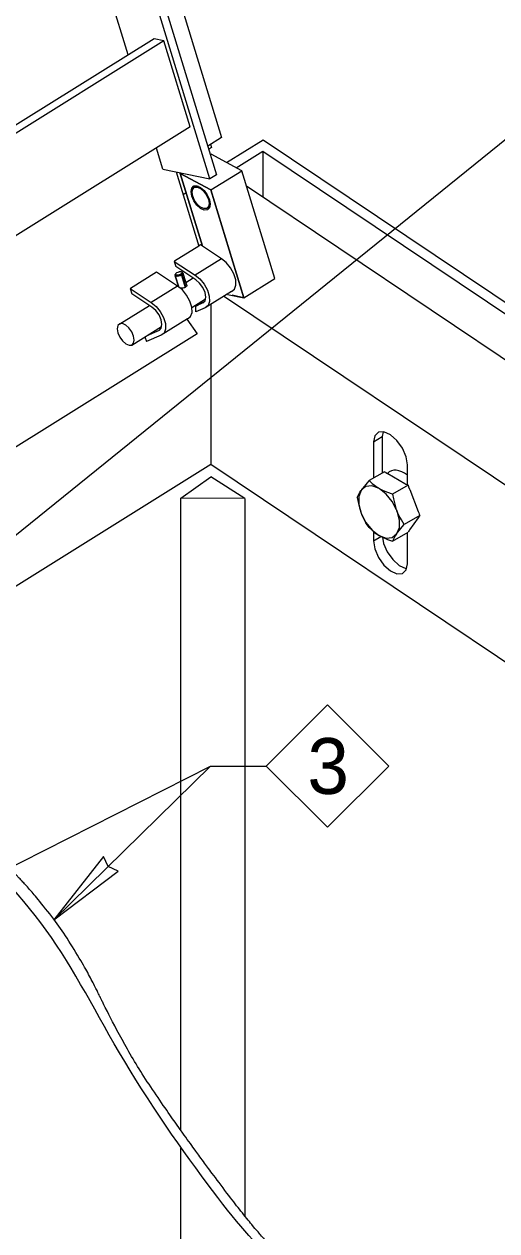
# Model space of a CAD drawing. Extents: x 99862 to 103151, y 100000 to 105076.
# Drawn here: x 100503.6 to 100639, y 100716.4 to 101062.4 of the extents above; entities that cross this region are included whole.
import ezdxf

# ---------------------------------------------------------------- set-up
doc = ezdxf.new("R2010")
doc.units = 0
for name, color, linetype in [('Level 1', 7, 'Continuous'), ('Level 11', 7, 'Continuous'), ('Level 15', 7, 'Continuous'), ('Level 20', 7, 'Continuous'), ('Level 4', 7, 'Continuous'), ('Level 6', 7, 'Continuous'), ('Level 9', 7, 'Continuous')]:
    doc.layers.add(name, color=color, linetype=linetype)

msp = doc.modelspace()

# ---------------------------------------------------------------- linework, layer by layer
at = {"layer": 'Level 1'}
for p, q in [((100533.35, 101053.56), (100518.86, 101101.05)), ((100540.84, 101058.24), (100346.19, 100936.6)), ((100543.64, 101057.65), (100346.79, 100934.64)), ((100543.34, 101020.83), (100541.5, 101026.88)), ((100571.97, 101026), (100571.97, 101012.75)), ((100556.91, 101024.96), (100557.13, 101025.1)), ((100556.91, 101024.96), (100557.13, 101025.1)), ((100556.91, 101024.96), (100557.13, 101025.1)), ((100543.34, 101020.83), (100556.78, 101018.01)), ((100547.1, 101020.04), (100553.59, 100998.77)), ((100548.32, 101019.59), (100548.55, 101019.74)), ((100548.32, 101019.59), (100548.55, 101019.74)), ((100548.32, 101019.59), (100554.67, 100998.77)), ((100557.1, 101014.86), (100565.92, 101020.37)), ((100557.1, 101014.86), (100565.92, 101020.37)), ((100553.49, 101015.87), (100552.71, 101015.82)), ((100553.06, 101016.06), (100553.08, 101016.06)), ((101027.48, 100706.93), (100567.28, 101015.9)), ((100550.03, 101013.99), (100549.12, 101013.42)), ((100555.85, 101009.55), (100556.17, 101009.75)), ((100553.59, 100998.77), (100546.64, 100994.43)), ((100546.59, 100994.39), (100552.58, 100990.43)), ((100546.97, 100990.82), (100547.06, 100990.9)), ((100549.14, 100990.92), (100549.13, 100990.93)), ((100550.17, 100987.53), (100549.14, 100990.92)), ((100546.82, 100990.5), (100546.87, 100990.63)), ((100546.88, 100990.21), (100546.83, 100990.37)), ((100546.97, 100990.82), (100546.87, 100990.63)), ((100546.88, 100990.2), (100546.88, 100990.21)), ((100546.88, 100990.2), (100546.88, 100990.21)), ((100546.88, 100990.2), (100547.91, 100987.02)), ((100547.91, 100987.02), (100546.88, 100990.2)), ((100546.96, 100990.73), (100547.16, 100990.09)), ((100547, 100990.61), (100547, 100990.6)), ((100547, 100990.6), (100547.16, 100990.09)), ((100550.17, 100987.53), (100549.66, 100989.22)), ((100549.93, 100988.32), (100552.02, 100989.62)), ((100566.53, 100983.95), (100575.35, 100989.46)), ((100533.98, 100986.56), (100540, 100982.58)), ((100562.99, 100985.78), (100555.43, 100981.06)), ((101023.58, 100673.63), (100560.7, 100984.4)), ((100530.96, 100976.46), (100539.45, 100981.77)), ((100551.61, 100981.14), (100555.54, 100983.6)), ((100554.62, 100982.54), (100553.93, 100982.59)), ((100554.8, 100982.46), (100554.81, 100982.46)), ((100557.03, 100982.02), (100557.03, 100936.2)), ((100550.42, 100977.93), (100542.86, 100973.21)), ((100550.21, 100977.8), (100553.1, 100973.63)), ((100553.1, 100973.63), (100354.56, 100849.56)), ((100542.23, 100974.6), (100542.23, 100974.6)), ((100538.2, 100972.76), (100538.62, 100971.37)), ((100381.31, 100826.39), (100557.03, 100936.2)), ((100557.03, 100936.2), (100740.05, 100813.32)), ((100548.46, 100926.44), (100557.03, 100932.64)), ((100566.76, 100926.43), (100557.03, 100932.64)), ((100566.76, 100926.43), (100548.46, 100926.44)), ((100548.46, 100745.22), (100548.46, 100926.44)), ((100548.46, 100687.98), (100548.46, 100740.07))]:
    msp.add_line(p, q, dxfattribs=at)
for points in [[(100515.46, 101160.82), (100558.67, 101019.19), (100556.78, 101018.01)], [(100519.44, 101163.3), (100560.14, 101029.92), (100556.16, 101027.43)], [(100556.78, 101018.01), (100513.57, 101159.64)], [(100551.18, 101032.93), (100543.64, 101057.65), (100540.84, 101058.24)], [(100551.18, 101032.93), (100551.18, 101032.93), (100354.33, 100909.91)], [(100561.52, 101022.73), (100572.06, 101029.21)], [(100572.09, 101029.27), (101031.93, 100720.54)], [(100556.98, 101027.95), (100557.27, 101027.02), (100556.44, 101026.5)], [(100564.32, 101021.22), (100571.97, 101026), (101030.8, 100717.96)], [(100575.35, 100989.46), (100575.35, 100989.46), (100565.92, 101020.37), (100557.13, 101025.1)], [(100561.85, 100984.93), (100566.53, 100983.95), (100575.35, 100989.46), (100565.92, 101020.37), (100557.13, 101025.1)], [(100554.67, 100998.77), (100548.32, 101019.59), (100548.55, 101019.74)], [(100554.67, 100998.77), (100548.32, 101019.59), (100557.1, 101014.86), (100566.53, 100983.95), (100563.16, 100984.66)], [(100566.53, 100983.95), (100557.1, 101014.86), (100548.32, 101019.59)], [(100556.86, 101010.77), (100556.66, 101009.75), (100556.07, 101009.17), (100555.18, 101009.11), (100554.14, 101009.58), (100553.09, 101010.5), (100552.2, 101011.74), (100551.6, 101013.11), (100551.39, 101014.4), (100551.59, 101015.42), (100552.18, 101016), (100553.06, 101016.06)], [(100555.85, 101009.55), (100555.07, 101009.5), (100554.14, 101009.91), (100553.21, 101010.73), (100552.41, 101011.84), (100551.88, 101013.05), (100551.69, 101014.2), (100551.87, 101015.1), (100552.39, 101015.62), (100552.71, 101015.82)], [(100552.39, 101015.62), (100553.18, 101015.68), (100554.11, 101015.26), (100555.04, 101014.44), (100555.83, 101013.34), (100556.36, 101012.12), (100556.55, 101010.97), (100556.37, 101010.07), (100555.85, 101009.55)], [(100553.06, 101016.06), (100554.11, 101015.6), (100555.15, 101014.67), (100556.04, 101013.43), (100556.64, 101012.06), (100556.86, 101010.77), (100556.86, 101010.77)], [(100556.17, 101009.75), (100556.17, 101009.75), (100556.69, 101010.27), (100556.83, 101010.95)], [(100562.99, 100985.78), (100563.83, 100986.41), (100564.24, 100987.56), (100564.18, 100989.11), (100563.65, 100990.85), (100562.72, 100992.57), (100561.49, 100994.07), (100560.13, 100995.15), (100554.11, 100999.14), (100553.58, 100998.81)], [(100546.64, 100994.43), (100546.63, 100994.42), (100546.59, 100994.39), (100547.03, 100992.93), (100547.04, 100992.92), (100547.04, 100992.92)], [(100560.13, 100995.15), (100552.58, 100990.43), (100553.94, 100989.35), (100555.16, 100987.85), (100556.09, 100986.12), (100556.62, 100984.38), (100556.69, 100982.84), (100556.27, 100981.69), (100555.43, 100981.06)], [(100541.54, 100991.28), (100541.54, 100991.28), (100534.03, 100986.59), (100533.98, 100986.56), (100534.43, 100985.1), (100534.43, 100985.09), (100534.43, 100985.09)], [(100550.42, 100977.93), (100551.26, 100978.55), (100551.67, 100979.71), (100551.61, 100981.25), (100551.08, 100982.99), (100550.14, 100984.72), (100548.92, 100986.21), (100547.56, 100987.3), (100541.54, 100991.28)], [(100547.06, 100990.9), (100546.97, 100990.74), (100546.96, 100990.73)], [(100554.81, 100982.46), (100554.81, 100982.46), (100555.43, 100983.05), (100555.64, 100984.1), (100555.42, 100985.45), (100554.8, 100986.88), (100553.86, 100988.17), (100552.77, 100989.13), (100547.04, 100992.92)], [(100548.99, 100991.2), (100548.88, 100991.28), (100548.67, 100991.36), (100548.56, 100991.38), (100548.53, 100991.38), (100548.27, 100991.39), (100548.25, 100991.39), (100547.92, 100991.34), (100547.91, 100991.33), (100547.57, 100991.22), (100547.57, 100991.22), (100547.27, 100991.07), (100547.06, 100990.9), (100547.06, 100990.9)], [(100548.82, 100991.18), (100548.81, 100991.19), (100548.75, 100991.31), (100548.73, 100991.31), (100548.56, 100991.38)], [(100548.59, 100990.87), (100548.75, 100991.02), (100548.76, 100991.04), (100548.82, 100991.18), (100548.98, 100990.65)], [(100548.98, 100990.65), (100548.81, 100991.19), (100548.97, 100990.65)], [(100549.14, 100990.92), (100549.06, 100990.74), (100549.05, 100990.72), (100548.84, 100990.53)], [(100548.99, 100991.2), (100549.06, 100991.08), (100549.13, 100990.93)], [(100549.14, 100990.92), (100549.13, 100990.93), (100549.14, 100990.92)], [(100546.82, 100990.5), (100546.83, 100990.37), (100547.81, 100987.1)], [(100548.66, 100990.41), (100548.3, 100990.25), (100548.26, 100990.24), (100547.86, 100990.12), (100547.83, 100990.12), (100547.44, 100990.07), (100547.42, 100990.07), (100547.1, 100990.1), (100547.09, 100990.1), (100546.88, 100990.2)], [(100546.96, 100990.73), (100547, 100990.61), (100547.16, 100990.09)], [(100547, 100990.6), (100547.16, 100990.52), (100547.17, 100990.51), (100547.42, 100990.49), (100547.45, 100990.49), (100547.75, 100990.53), (100547.79, 100990.53), (100548.09, 100990.62), (100548.14, 100990.64), (100548.41, 100990.76), (100548.46, 100990.72), (100548.5, 100990.68), (100548.51, 100990.67), (100548.54, 100990.63), (100548.58, 100990.58), (100548.6, 100990.55), (100548.61, 100990.52), (100548.64, 100990.47), (100548.66, 100990.41), (100549.73, 100986.9)], [(100548.59, 100990.87), (100549.74, 100987.12), (100549.74, 100987.12)], [(100549.91, 100987.02), (100548.84, 100990.53), (100548.82, 100990.59), (100548.79, 100990.64), (100548.78, 100990.66), (100548.76, 100990.7), (100548.72, 100990.75), (100548.69, 100990.78), (100548.68, 100990.8), (100548.64, 100990.84), (100548.59, 100990.87)], [(100550.14, 100987.65), (100550.16, 100987.6), (100549.33, 100990.29)], [(100550.16, 100987.6), (100550.17, 100987.53), (100550.18, 100987.51), (100550.17, 100987.38), (100550.13, 100987.28), (100550.12, 100987.27), (100550.05, 100987.16), (100550.03, 100987.13), (100549.91, 100987.02), (100549.74, 100987.12)], [(100542.23, 100974.6), (100542.23, 100974.6), (100542.85, 100975.2), (100543.07, 100976.25), (100542.85, 100977.59), (100542.22, 100979.02), (100541.29, 100980.32), (100540.2, 100981.27), (100534.43, 100985.09)], [(100547.56, 100987.3), (100540, 100982.58), (100541.36, 100981.49), (100542.59, 100979.99), (100543.52, 100978.27), (100544.05, 100976.53), (100544.11, 100974.99), (100543.7, 100973.83), (100542.86, 100973.21)], [(100549.73, 100986.9), (100549.67, 100986.87), (100549.49, 100986.81), (100549.32, 100986.76), (100549.3, 100986.76), (100549.09, 100986.73), (100548.91, 100986.71), (100548.87, 100986.71), (100548.69, 100986.71), (100548.54, 100986.71), (100548.44, 100986.72), (100548.35, 100986.73), (100548.26, 100986.74)], [(100552.78, 100979.92), (100552.78, 100979.91), (100552.78, 100980.86), (100552.78, 100981.58), (100554.62, 100982.54), (100555.41, 100983.04)], [(100554.81, 100982.46), (100554.8, 100982.46), (100552.78, 100981.58)], [(100555.43, 100981.06), (100555.43, 100981.06), (100552.78, 100979.91)], [(100530.96, 100976.46), (100530.43, 100975.95), (100530.26, 100975.04), (100530.45, 100973.9), (100530.98, 100972.68), (100531.77, 100971.57), (100532.7, 100970.75), (100533.63, 100970.34), (100534.41, 100970.39), (100542.97, 100975.74)], [(100534.41, 100970.39), (100534.94, 100970.91), (100535.12, 100971.81), (100534.92, 100972.96), (100534.39, 100974.18), (100533.6, 100975.28), (100532.67, 100976.1), (100531.74, 100976.52), (100530.96, 100976.46)], [(100542.23, 100974.6), (100542.23, 100974.6), (100538.7, 100973.07)], [(100542.86, 100973.21), (100542.86, 100973.21), (100538.62, 100971.37)], [(100605.09, 100945.42), (100604.03, 100944.4), (100603.66, 100942.61), (100606.18, 100944.18)], [(100603.66, 100942.61), (100603.66, 100932.25)], [(100613.38, 100930.09), (100613.38, 100936.08), (100613.01, 100938.37), (100611.96, 100940.81), (100610.38, 100943.02), (100608.52, 100944.68), (100606.66, 100945.52), (100605.09, 100945.42)], [(100606.46, 100945.51), (100606.18, 100944.18), (100606.18, 100933.71)], [(100606.18, 100928.77), (100606.18, 100928.53)], [(100566.76, 100926.43), (100566.76, 100720.69)], [(100603.66, 100917.01), (100603.66, 100914.22), (100605.76, 100915.53)], [(100606.26, 100915.3), (100606.55, 100913.51), (100607.6, 100911.07), (100609.18, 100908.85), (100611.04, 100907.2), (100612.9, 100906.36), (100613.11, 100906.37)], [(100611.96, 100904.88), (100611.96, 100904.88), (100613.01, 100905.9), (100613.38, 100907.7), (100613.38, 100916.62)], [(100603.66, 100914.22), (100604.03, 100911.93), (100605.09, 100909.49), (100606.66, 100907.28), (100608.52, 100905.63), (100610.38, 100904.78), (100611.96, 100904.88)]]:
    msp.add_lwpolyline(points, dxfattribs=at)
at = {"layer": 'Level 11'}
for points in [[(100619.03, 100616.15), (100627.15, 100624.81), (100630.29, 100628.34), (100640.98, 100641.39), (100661.22, 100680.29), (100678.37, 100718.73)], [(100624.53, 100616.24), (100629.73, 100621.87), (100629.84, 100621.99), (100631.03, 100623.32), (100632.11, 100624.53), (100633.69, 100626.36), (100634.47, 100627.28), (100635.36, 100628.36), (100635.81, 100628.89), (100636, 100629.12), (100636.12, 100629.28), (100636.18, 100629.35), (100636.82, 100630.13), (100637.41, 100630.92), (100638.67, 100632.69), (100639.33, 100633.67), (100641.43, 100636.91), (100642.98, 100639.45), (100648.01, 100648.09), (100651.88, 100655.21), (100664.38, 100679.28), (100673.86, 100698.94), (100682.8, 100719.04), (100683.07, 100719.66), (100683.34, 100720.28)]]:
    msp.add_open_spline(points, degree=3, dxfattribs=at)
at = {"layer": 'Level 15'}
for p, q in [((100458.92, 100881.7), (100656.15, 101041.32)), ((100456.13, 100798.43), (100556.94, 100849.67)), ((100512.12, 100805.61), (100556.94, 100849.67)), ((100556.94, 100849.67), (100572.94, 100849.67))]:
    msp.add_line(p, q, dxfattribs=at)
msp.add_lwpolyline([(100512.12, 100805.61), (100530.49, 100819.48), (100527.65, 100820.87), (100526.31, 100823.74)], close=True, dxfattribs=at)
msp.add_ellipse((100612.41, 100927.07), major_axis=(-4.08, 7.06), ratio=0.57735, start_param=5.32771, end_param=6.466951, dxfattribs=at)
at = {"layer": 'Level 20'}
msp.add_lwpolyline([(100590.5, 100867.23), (100608.05, 100849.67), (100590.5, 100832.12), (100572.94, 100849.67)], close=True, dxfattribs=at)
at = {"layer": 'Level 4'}
for points in [[(100699.37, 100799.85), (100689.61, 100780.31), (100686.61, 100773.59), (100671.42, 100736.29), (100663.59, 100719.01), (100642.72, 100699.52), (100607.96, 100695.63), (100576.55, 100705.21), (100563.7, 100718.98), (100531.72, 100763.25), (100513.08, 100802.01), (100484.24, 100831.76), (100457.17, 100857.36), (100451.77, 100869.41), (100452.8, 100878.95)], [(100694.43, 100796.66), (100693.21, 100794.21), (100692.11, 100792), (100689.01, 100785.74), (100687.46, 100782.59), (100686.23, 100780.03), (100686.02, 100779.59), (100685.76, 100779.03), (100685.68, 100778.85), (100685.57, 100778.62), (100685.54, 100778.55), (100685.47, 100778.41), (100685.45, 100778.34), (100685.18, 100777.74), (100684.87, 100777.02), (100683.69, 100774.25), (100682.59, 100771.58), (100680.44, 100766.36), (100679.64, 100764.41), (100678.32, 100761.18), (100677.62, 100759.48), (100676.89, 100757.67), (100676.38, 100756.44), (100676.13, 100755.81), (100673.85, 100750.23), (100672.03, 100745.81), (100668.79, 100738.09), (100667.37, 100734.77), (100665.86, 100731.32), (100665.57, 100730.67), (100665.15, 100729.74), (100664.98, 100729.36), (100664.82, 100729), (100664.75, 100728.85), (100664.72, 100728.79), (100664.63, 100728.59), (100664.07, 100727.39), (100663.4, 100726.16), (100661.33, 100722.8), (100659.6, 100720.47), (100656.46, 100716.84), (100655.32, 100715.61), (100653.47, 100713.73), (100652.51, 100712.79), (100651.5, 100711.83), (100651.08, 100711.43), (100651, 100711.36), (100650.83, 100711.21), (100650.59, 100710.98), (100650.34, 100710.76), (100647.49, 100708.28), (100644.46, 100706.33), (100637.62, 100703.2), (100633.82, 100702.02), (100628.56, 100701.04), (100627.48, 100700.87), (100625.82, 100700.65), (100625.27, 100700.58), (100624.13, 100700.46), (100621.31, 100700.18), (100618.52, 100700.04), (100611.9, 100699.97), (100607.59, 100700.28), (100601.26, 100701.27), (100599.17, 100701.69), (100596.07, 100702.45), (100595.04, 100702.72), (100593, 100703.32), (100591.97, 100703.64), (100587.04, 100705.26), (100583.63, 100706.66), (100577.89, 100709.6), (100575.56, 100711.15), (100573.31, 100713.13), (100572.9, 100713.53), (100572.46, 100713.98), (100572.42, 100714.03), (100572.32, 100714.13), (100572.27, 100714.19), (100572.12, 100714.35), (100571.8, 100714.7), (100571.46, 100715.08), (100570.29, 100716.4), (100569.21, 100717.68), (100565.56, 100722.16), (100562.58, 100726), (100557.33, 100733.02), (100555.45, 100735.57), (100552.43, 100739.71), (100551.39, 100741.14), (100549.25, 100744.11), (100548.2, 100745.58), (100538.95, 100758.76), (100532.2, 100769.84), (100526.58, 100780.94), (100526.09, 100781.92), (100525.61, 100782.89), (100525.3, 100783.53), (100525.15, 100783.85), (100524.34, 100785.52), (100522.35, 100789.47), (100520.2, 100793.29), (100515.69, 100800.73), (100512.4, 100805.45), (100507.02, 100812.14), (100505.16, 100814.31), (100502.74, 100816.94), (100502.01, 100817.73), (100501.27, 100818.5), (100500.77, 100819.02), (100500.53, 100819.27), (100499.31, 100820.52), (100494.45, 100825.51), (100485.84, 100834.16), (100478.38, 100841.4), (100473.77, 100845.79), (100472.84, 100846.66), (100471.08, 100848.34), (100470.24, 100849.16), (100467.82, 100851.54), (100466.36, 100853.03), (100462.43, 100857.21), (100460.42, 100859.62), (100458.34, 100862.57), (100457.81, 100863.44), (100457.34, 100864.34), (100457.25, 100864.52), (100457.1, 100864.84), (100457.03, 100865.02), (100456.81, 100865.55), (100456.67, 100865.92), (100456.05, 100867.85), (100455.72, 100869.65), (100455.45, 100873.76), (100455.51, 100876.07), (100455.78, 100878.63)]]:
    msp.add_open_spline(points, degree=3, dxfattribs=at)
at = {"layer": 'Level 6'}
for p, q in [((100603.81, 100929.8), (100603.81, 100929.8)), ((100611.56, 100917.85), (100611.55, 100917.86))]:
    msp.add_line(p, q, dxfattribs=at)
for points in [[(100606.81, 100934.07), (100606.81, 100934.07), (100607.07, 100933.92), (100607.14, 100933.88), (100607.66, 100933.58), (100607.68, 100933.56), (100607.77, 100933.51), (100612.67, 100930.68), (100612.95, 100930.53), (100613.22, 100930.37), (100613.54, 100930.18), (100613.68, 100929.84), (100613.72, 100929.74), (100613.97, 100929.08), (100613.99, 100929.04), (100614.02, 100928.96), (100616.47, 100922.64), (100616.61, 100922.27), (100616.75, 100921.91), (100616.91, 100921.5), (100616.8, 100921.34), (100616.73, 100921.24), (100616.73, 100921.23), (100616.45, 100920.85), (100614, 100917.36), (100613.89, 100917.2), (100613.72, 100916.97), (100613.54, 100916.71)], [(100605.73, 100928.89), (100605.73, 100929)]]:
    msp.add_lwpolyline(points, dxfattribs=at)
at = {"layer": 'Level 9'}
for p, q in [((100616.91, 100921.5), (100612.48, 100918.94)), ((100605.46, 100915.66), (100605.26, 100915.77))]:
    msp.add_line(p, q, dxfattribs=at)
for points in [[(100606.81, 100934.07), (100602.38, 100931.51), (100601.78, 100930.83), (100601.52, 100930.51), (100600.46, 100929.21), (100600.25, 100928.92), (100600.1, 100928.71)], [(100599.01, 100926.72), (100599.36, 100927.4), (100599.78, 100928.22), (100600.1, 100928.71)], [(100600.1, 100928.71), (100599.47, 100926.96), (100599.48, 100924.67), (100600.13, 100922.18)], [(100602.38, 100931.51), (100603.06, 100930.84), (100603.28, 100930.67), (100604.99, 100929.4), (100605.06, 100929.36), (100603.18, 100930.02), (100601.5, 100929.87), (100600.25, 100928.92)], [(100613.54, 100930.18), (100609.11, 100927.62), (100607.73, 100928.14), (100606.49, 100928.61), (100605.38, 100929.17), (100605.06, 100929.36)], [(100609.11, 100927.62), (100609.34, 100926.29), (100609.44, 100925.91), (100610.16, 100923.28), (100610.21, 100923.14), (100608.96, 100925.55), (100607.27, 100927.66), (100605.38, 100929.17)], [(100599.01, 100926.72), (100599.36, 100925), (100599.64, 100923.67), (100600.13, 100922.18), (100600.21, 100921.98)], [(100602.38, 100918.04), (100601.68, 100919.09), (100601.5, 100919.44), (100600.29, 100921.78), (100600.21, 100921.98)], [(100600.21, 100921.98), (100601.49, 100919.52), (100603.25, 100917.33), (100605.26, 100915.77), (100607.27, 100915.04), (100609.02, 100915.22), (100610.28, 100916.25), (100609.88, 100915.65), (100609.5, 100914.91), (100609.11, 100914.15)], [(100610.21, 100923.14), (100610.34, 100922.83), (100610.98, 100920.3), (100610.96, 100917.99), (100610.28, 100916.25), (100611.49, 100917.81), (100611.51, 100917.83), (100611.88, 100918.26), (100612.48, 100918.94), (100611.68, 100920.26), (100610.94, 100921.48), (100610.34, 100922.83)], [(100602.38, 100918.04), (100603.36, 100917.17), (100604.06, 100916.55), (100605.26, 100915.77)], [(100605.46, 100915.66), (100607.67, 100914.67), (100607.95, 100914.55), (100609.11, 100914.15), (100613.54, 100916.71)]]:
    msp.add_lwpolyline(points, dxfattribs=at)

# ---------------------------------------------------------------- texts
at = {"layer": 'Level 20'}
msp.add_text('3', height=16, dxfattribs=at).set_placement((100584.72, 100841.68))

doc.saveas('drawing.dxf')
